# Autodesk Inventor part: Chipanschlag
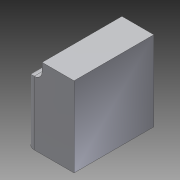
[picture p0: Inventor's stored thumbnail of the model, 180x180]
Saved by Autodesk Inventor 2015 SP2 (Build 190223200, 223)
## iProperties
Created: 2016-01
Part Number: Chipanschlag
Material: PC/ABS-Kunststoff
Document SubType Name: Modeling
Designer: rYan
Mass: 0.134425 g
Surface Area: 4.19717 cm^2
Volume: 0.376252 cm^3
Density: 0.357273 g/cm^3
Appearance: Glatt - weiß
Author: rYan
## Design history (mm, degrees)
sketch "Skizze1"
  geometry: L1 (0, 0)-(10, 0); L2 (10, 0)-(10, 10); L3 (10, 10)-(0, 10); L4 (0, 10)-(0, 0)
  constraints: 8 end point, 2 parallel, 1 horizontal, 1 perpendicular
  dimensions: "d0" = 10 distance of L3.end L2.end; "d1" = 10 distance of L2.end L1.end
extrude "Extrusion1" new body sketch "Skizze1" stored distance "d2" = 6; taper "d3" = 0 deg
sketch "Skizze2"
  geometry: L1 (6, 0)-(0, 0) reference; L2 (0, -10)-(0, 0) reference; L3 (0, -10)-(6, -10) reference; L4 (6, 0)-(6, -10) reference; L5 (3, -10)-(3, 0); 2 further points
  constraints: 2 end point, 2 point on line, 1 midpoint
  dimensions: "d4" = 2 distance from line of L3 point (3, -8); "d5" = 6 distance of point (3, -2) point (3, -8)
hole "Bohrung1" sketch "Skizze2" at (3, -8), (3, -2) diameter "d6" = 2.459; stored, may be unused: countersink angle "d10" = 90 deg, drill point angle "d12" = 118 deg; dims "d7" = 6, "d8" = 4, "d9" = 2, "d11" = 5
sketch "Skizze3"
  geometry: L1 (0, 0)-(6, 0) reference; L2 (6, 10)-(6, 0) reference; L3 (0, 10)-(6, 10) reference; L4 (0, 0)-(0, 10) reference; L5 (0, 10)-(2, 10); L6 (2, 10)-(2, 0); L7 (2, 0)-(0, 0); L8 (0, 0)-(0, 10); 1 further point
  constraints: 8 end point, 2 parallel, 1 horizontal, 1 perpendicular, 1 point on line
  dimensions: "d13" = 2 distance between parallel lines of L4 L6
extrude "Extrusion2" cut sketch "Skizze3" distance "d14" = 2; taper "d15" = 0 deg
fillet "Rundung1" dims "d16" = 1
node "Volumenkörper1"
node "Projizierte Kontur1"
node "Projizierte Kontur2"
